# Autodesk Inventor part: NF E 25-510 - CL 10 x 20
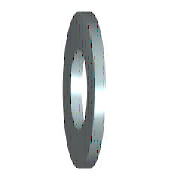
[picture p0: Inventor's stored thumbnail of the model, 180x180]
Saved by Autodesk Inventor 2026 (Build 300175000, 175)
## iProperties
IsCustomPart: 0
Created: 2025-01
Part Number: NF E 25-510 - CL 10 x 20
Material: Acier, doux
Description: Rondelles cuvette
Document SubType Name: Modeling
Standard: NF E 25-510
Designer: thierry.jost
Standards Organization: AFNOR
Language: fr-FR
Size Designation: CL 10 x 20
Categories: <MemberInstance><Categories><Category DisplayName="Visserie" InternalName="e4da775c-781d-43d5-af7c-5136215cf5a6" Mnemonic="FSTN"><Category DisplayName="Rondelle
Density: 7.85 g/cm^3
Appearance: Semi-poli
Author: thierry.jost
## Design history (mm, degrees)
body "Solid1"
sketch "Esquisse"
  geometry: C1 r 10 at (0, 0); C2 r 5.25 at (0, 0); 1 further point
  constraints: 2 centre point, 2 coincident
  dimensions: "d0" = 10.5 diameter of C2 (= SD1); "d1" = 20 diameter of C1 (= SD2)
extrude "Corps" new body sketch "Esquisse" distance "d2" = 2.2 (= SD); taper "d3" = 0 deg
workaxis "Work Axis1"
workplane "Work Plane1"
other parameters: "SD1" = 10.5 [user parameter; used in 1 equation term], "SD2" = 20 [user parameter; used in 1 equation term], "SD" = 2.2 [user parameter; used in 1 equation term], "d4" = 0, "d5" = 0, "d6" = 0, "d7" = 0
